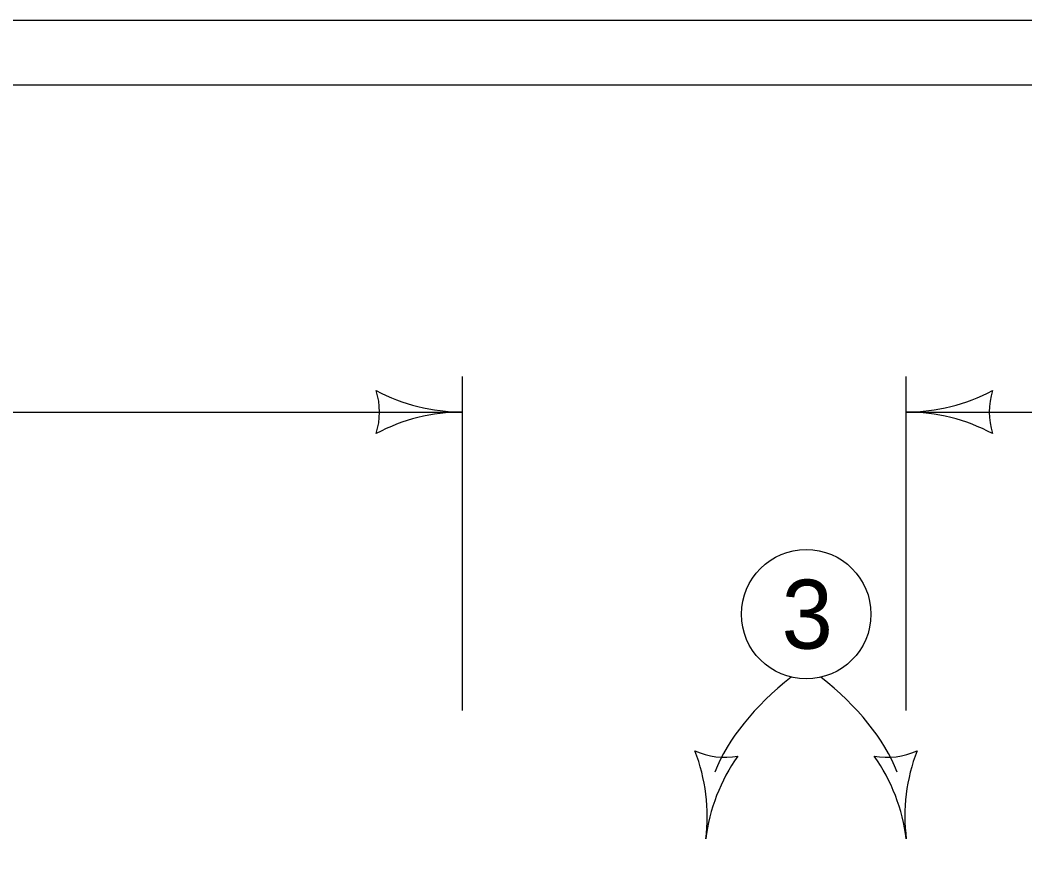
# Model space of a CAD drawing. Extents: x 9538 to 81668, y 7600 to 11751.
# Drawn here: x 11290.7 to 11523.6, y 9750.9 to 9944 of the extents above; entities that cross this region are included whole.
import ezdxf

# ---------------------------------------------------------------- set-up
doc = ezdxf.new("R2010")
doc.units = 0
for name, color, linetype in [('Default', 7, 'Continuous'), ('DsnShtMinorGrid13', 7, 'Continuous'), ('dsnStdDimension', 7, 'Continuous'), ('dsnStdShading', 7, 'Continuous')]:
    doc.layers.add(name, color=color, linetype=linetype)

msp = doc.modelspace()

# ---------------------------------------------------------------- linework, layer by layer
at = {"layer": 'Default'}
msp.add_lwpolyline([(10132.52, 9944.02), (13267.53, 9944.02), (13267.53, 7924.02), (10132.52, 7924.02)], close=True, dxfattribs=at)
at = {"layer": 'DsnShtMinorGrid13'}
msp.add_circle((11472.9, 9806.28), 15, dxfattribs=at)
for centre, radius, start, end in [((11454.01, 9789.53), 16.42, 245.1764, 280.6431), ((11407.43, 9759.41), 42.5, 352.9098, 20.9823), ((11491.69, 9789.53), 16.42, 259.3569, 294.8236), ((11538.27, 9759.41), 42.5, 159.0177, 187.0902), ((11491.78, 9748.92), 42.5, 144.8373, 172.9098), ((11453.92, 9748.92), 42.5, 7.0902, 35.1627)]:
    msp.add_arc(centre, radius, start, end, dxfattribs=at)
for centre, major_axis, start_param, end_param in [((11538.76, 9766.51), (-89.15, -12.34), 5.523141, 5.97728), ((11406.94, 9766.51), (89.15, -12.34), 0.305948, 0.759638)]:
    msp.add_ellipse(centre, major_axis=major_axis, ratio=0.555556, start_param=start_param, end_param=end_param, dxfattribs=at)
at = {"layer": 'dsnStdDimension'}
for p, q in [((11393.21, 9783.96), (11393.21, 9861.36)), ((11496.09, 9783.96), (11496.09, 9861.36)), ((10370.79, 9853.15), (11393.21, 9853.15)), ((11496.09, 9853.15), (11632.09, 9853.15))]:
    msp.add_line(p, q, dxfattribs=at)
for centre, radius, start, end in [((11357.57, 9853.15), 16.42, 342.2666, 17.7333), ((11393.21, 9895.65), 42.5, 241.9275, 270), ((11496.09, 9895.65), 42.5, 270, 298.0725), ((11531.73, 9853.15), 16.42, 162.2666, 197.7334), ((11393.21, 9810.65), 42.5, 90, 118.0725), ((11496.09, 9810.65), 42.5, 61.9275, 90)]:
    msp.add_arc(centre, radius, start, end, dxfattribs=at)
at = {"layer": 'dsnStdShading'}
msp.add_line((10147.52, 9929.02), (13243.21, 9929.02), dxfattribs=at)

# ---------------------------------------------------------------- texts
at = {"layer": 'DsnShtMinorGrid13'}
msp.add_text('3', height=16, dxfattribs=at).set_placement((11467.19, 9798.28))

doc.saveas('drawing.dxf')
